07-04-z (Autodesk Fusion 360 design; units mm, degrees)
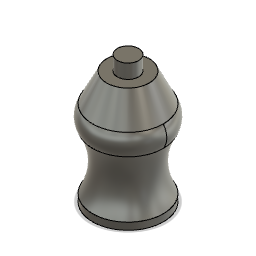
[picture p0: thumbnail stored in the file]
sketch "スケッチ1" plane through (0, 0, 0) normal (0, 1, 0) x axis (1, 0, 0)
  circle C1 centre (0, 0) radius 25
  point P1 (0, 0)
  point P2 (0, 0)
  coincident P1 P2
  dimension "d1" diameter C1 = 50
extrude "押し出し1" new body sketch "スケッチ1" along normal blind 5
work_plane "作業平面1" AlongDistance 20
sketch "スケッチ2" plane through (0, 25, 0) normal (0, 1, 0) x axis (1, 0, 0)
  circle C1 centre (0, 0) radius 20
  point P1 (0, 0)
  point P2 (0, 0)
  coincident P1 P2
  dimension "d5" diameter C1 = 40
work_plane "作業平面2" AlongDistance 20
sketch "スケッチ3" plane through (0, 45, 0) normal (0, 1, 0) x axis (1, 0, 0)
  circle C1 centre (0, 0) radius 25
loft "ロフト1" sketch "スケッチ2" + "スケッチ3"
work_plane "作業平面3" AlongDistance 15
sketch "スケッチ4" plane through (0, 60, 0) normal (0, 1, 0) x axis (1, 0, 0)
  circle C1 centre (0, 0) radius 25
sketch "スケッチ5" plane through (0, 0, 0) normal (0, 0, 1) x axis (1, 0, 0)
  line L1 (-25, 60) -> (25, 60)
  line L2 (25, 45) -> (-25, 45)
  arc A1 centre (-14.3816, 52.5) radius 13 clockwise from (-25, 45) to (-25, 60)
  arc A2 centre (14.3816, 52.5) radius 13 clockwise from (25, 60) to (25, 45)
  point P2 (-25, 60)
  point P9 (-25, 60)
  point P3 (-25, 45)
  point P10 (-25, 45)
  point P5 (25, 60)
  point P8 (25, 60)
  point P6 (25, 45)
  point P11 (25, 45)
  coincident P2 P9
  coincident P3 P10
  coincident P5 P8
  coincident P6 P11
  equal A1 A2
  dimension "d8" radius A1 = 13
sketch "スケッチ6" plane through (0, 0, 0) normal (1, 0, 0) x axis (0, 0, -1)
  line L1 (-25, 60) -> (25, 60)
  line L2 (25, 45) -> (-25, 45)
  arc A1 centre (-14.3816, 52.5) radius 13 clockwise from (-25, 45) to (-25, 60)
  arc A2 centre (14.3816, 52.5) radius 13 clockwise from (25, 60) to (25, 45)
  point P2 (-25, 60)
  point P9 (-25, 60)
  point P3 (-25, 45)
  point P10 (-25, 45)
  point P6 (25, 45)
  point P11 (25, 45)
  point P5 (25, 60)
  point P8 (25, 60)
  coincident P2 P9
  coincident P3 P10
  coincident P6 P11
  coincident P5 P8
  equal A1 A2
  dimension "d9" radius A1 = 13
loft "ロフト2" sketch "スケッチ4"
work_plane "作業平面4" AlongDistance 20
sketch "スケッチ7" plane through (0, 80, 0) normal (0, 1, 0) x axis (1, 0, 0)
  circle C1 centre (0, 0) radius 15
  point P1 (0, 0)
  point P2 (0, 0)
  coincident P1 P2
  dimension "d12" diameter C1 = 30
loft "ロフト3" sketch "スケッチ7"
sketch "スケッチ8" plane through (0, 80, 0) normal (0, 1, 0) x axis (-1, 0, 0)
  circle C1 centre (0, 0) radius 15
  circle C2 centre (0, 0) radius 7.5
  point P1 (0, 0)
  point P3 (0, 0)
  coincident P1 P3
  dimension "d13" diameter C2 = 15
extrude "押し出し2" add sketch "スケッチ8" profile of C2 along normal blind 10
